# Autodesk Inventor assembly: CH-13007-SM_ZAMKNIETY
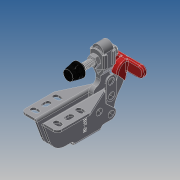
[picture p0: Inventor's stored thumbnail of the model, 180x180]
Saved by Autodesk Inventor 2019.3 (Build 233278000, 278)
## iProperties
Company: Microsoft
Created: 2017-11
Part Number: CH-13007-SM_ZAMKNIETY
Material: Ogólny
Description: STEP AP203
Document SubType Name: Assembly
Designer: Admin
Sending System: SolidWorks 2015
Preprocessor: SwSTEP 2.0
Title: CH-13007-SM.STEP
Author: Windows
Revision Number: ÈÎºÎ
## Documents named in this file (7)
- E:\SERWER_ZAPAS\MODELE brakujace\brakujące stepy_08012019\CH-13007-SM\CH-13007-SM_ZAMKNIETY.iam
- E:\SERWER_ZAPAS\MODELE brakujace\brakujące stepy_08012019\CH-13007-SM\13007-SMµ××ù.ipt
- E:\SERWER_ZAPAS\MODELE brakujace\brakujące stepy_08012019\CH-13007-SM\CH-13007-02 U-BAR.ipt
- E:\SERWER_ZAPAS\MODELE brakujace\brakujące stepy_08012019\CH-13007-SM\CH-13007-04 CONNECTING-PLATE.ipt
- E:\SERWER_ZAPAS\MODELE brakujace\brakujące stepy_08012019\CH-13007-SM\CH-13007-03 T-HANDLE.ipt
- E:\SERWER_ZAPAS\MODELE brakujace\brakujące stepy_08012019\CH-13007-SM\CH-13007-05 .ipt
- E:\SERWER_ZAPAS\MODELE brakujace\brakujące stepy_08012019\CH-13007-SM\400.iam
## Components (10 placed, 10 different names)
1. 13007-SMµ××ù_1
2. CH-13007-02 U-BAR_2
3. CH-13007-04 CONNECTING-PLATE_3
4. CH-13007-04 CONNECTING-PLATE_4
5. CH-13007-03 T-HANDLE_5
6. CH-13007-05 _6
7. CH-13007-05 _7
8. CH-13007-05 _8
9. CH-13007-05 _9
10. 400_10 [sub-assembly]
